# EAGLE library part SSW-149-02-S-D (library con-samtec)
THROUGH-HOLE .025" SQ POST SOCKET Source: Samtec SSW.pdf
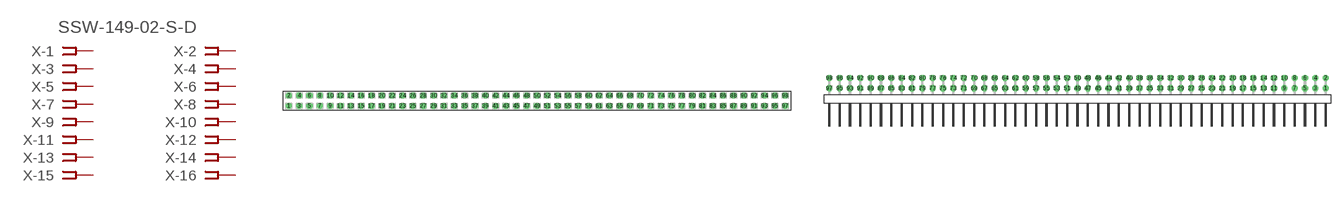
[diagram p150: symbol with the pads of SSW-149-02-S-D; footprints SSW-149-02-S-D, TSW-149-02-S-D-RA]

Designator prefix X; gates -1=FPINV -2=FPIN -3=FPIN -4=FPIN -5=FPIN -6=FPIN -7=FPIN -8=FPIN -9=FPIN -10=FPIN -11=FPIN -12=FPIN -13=FPIN -14=FPIN -15=FPIN -16=FPIN -17=FPIN -18=FPIN -19=FPIN -20=FPIN -21=FPIN -22=FPIN -23=FPIN -24=FPIN -25=FPIN -26=FPIN -27=FPIN -28=FPIN -29=FPIN -30=FPIN -31=FPIN -32=FPIN -33=FPIN -34=FPIN -35=FPIN -36=FPIN -37=FPIN -38=FPIN -39=FPIN -40=FPIN -41=FPIN -42=FPIN -43=FPIN -44=FPIN -45=FPIN -46=FPIN -47=FPIN -48=FPIN -49=FPIN -50=FPIN -51=FPIN -52=FPIN -53=FPIN -54=FPIN -55=FPIN -56=FPIN -57=FPIN -58=FPIN -59=FPIN -60=FPIN -61=FPIN -62=FPIN -63=FPIN -64=FPIN -65=FPIN -66=FPIN -67=FPIN -68=FPIN -69=FPIN -70=FPIN -71=FPIN -72=FPIN -73=FPIN -74=FPIN -75=FPIN -76=FPIN -77=FPIN -78=FPIN -79=FPIN -80=FPIN -81=FPIN -82=FPIN -83=FPIN -84=FPIN -85=FPIN -86=FPIN -87=FPIN -88=FPIN -89=FPIN -90=FPIN -91=FPIN -92=FPIN -93=FPIN -94=FPIN -95=FPIN -96=FPIN -97=FPIN -98=FPIN

## SSW-149-02-S-D (OC_FARNELL: unknown; OC_NEWARK: unknown)  [SSW-149-02-S-D]
1  -1:1  pas
2  -2:1  pas
3  -3:1  pas
4  -4:1  pas
5  -5:1  pas
6  -6:1  pas
7  -7:1  pas
8  -8:1  pas
9  -9:1  pas
10  -10:1  pas
11  -11:1  pas
12  -12:1  pas
13  -13:1  pas
14  -14:1  pas
15  -15:1  pas
16  -16:1  pas
17  -17:1  pas
18  -18:1  pas
19  -19:1  pas
20  -20:1  pas
21  -21:1  pas
22  -22:1  pas
23  -23:1  pas
24  -24:1  pas
25  -25:1  pas
26  -26:1  pas
27  -27:1  pas
28  -28:1  pas
29  -29:1  pas
30  -30:1  pas
31  -31:1  pas
32  -32:1  pas
33  -33:1  pas
34  -34:1  pas
35  -35:1  pas
36  -36:1  pas
37  -37:1  pas
38  -38:1  pas
39  -39:1  pas
40  -40:1  pas
41  -41:1  pas
42  -42:1  pas
43  -43:1  pas
44  -44:1  pas
45  -45:1  pas
46  -46:1  pas
47  -47:1  pas
48  -48:1  pas
49  -49:1  pas
50  -50:1  pas
51  -51:1  pas
52  -52:1  pas
53  -53:1  pas
54  -54:1  pas
55  -55:1  pas
56  -56:1  pas
57  -57:1  pas
58  -58:1  pas
59  -59:1  pas
60  -60:1  pas
61  -61:1  pas
62  -62:1  pas
63  -63:1  pas
64  -64:1  pas
65  -65:1  pas
66  -66:1  pas
67  -67:1  pas
68  -68:1  pas
69  -69:1  pas
70  -70:1  pas
71  -71:1  pas
72  -72:1  pas
73  -73:1  pas
74  -74:1  pas
75  -75:1  pas
76  -76:1  pas
77  -77:1  pas
78  -78:1  pas
79  -79:1  pas
80  -80:1  pas
81  -81:1  pas
82  -82:1  pas
83  -83:1  pas
84  -84:1  pas
85  -85:1  pas
86  -86:1  pas
87  -87:1  pas
88  -88:1  pas
89  -89:1  pas
90  -90:1  pas
91  -91:1  pas
92  -92:1  pas
93  -93:1  pas
94  -94:1  pas
95  -95:1  pas
96  -96:1  pas
97  -97:1  pas
98  -98:1  pas

## SSW-149-02-S-D-RA (MPN: SSW-149-02-S-D-RA; OC_FARNELL: unknown; OC_NEWARK: 12P0058)  [TSW-149-02-S-D-RA]
Pads as for SSW-149-02-S-D

## Footprint SSW-149-02-S-D (pad centres in mm)
THROUGH-HOLE .025" SQ POST SOCKET Source: Samtec SSW.pdf
drill 1 pad 1.5 octagon: 1 -60.96,-1.27; 2 -60.96,1.27; 3 -58.42,-1.27; 4 -58.42,1.27; 5 -55.88,-1.27; 6 -55.88,1.27; 7 -53.34,-1.27; 8 -53.34,1.27; 9 -50.8,-1.27; 10 -50.8,1.27; 11 -48.26,-1.27; 12 -48.26,1.27; 13 -45.72,-1.27; 14 -45.72,1.27; 15 -43.18,-1.27; 16 -43.18,1.27; 17 -40.64,-1.27; 18 -40.64,1.27; 19 -38.1,-1.27; 20 -38.1,1.27; 21 -35.56,-1.27; 22 -35.56,1.27; 23 -33.02,-1.27; 24 -33.02,1.27; 25 -30.48,-1.27; 26 -30.48,1.27; 27 -27.94,-1.27; 28 -27.94,1.27; 29 -25.4,-1.27; 30 -25.4,1.27; 31 -22.86,-1.27; 32 -22.86,1.27; 33 -20.32,-1.27; 34 -20.32,1.27; 35 -17.78,-1.27; 36 -17.78,1.27; 37 -15.24,-1.27; 38 -15.24,1.27; 39 -12.7,-1.27; 40 -12.7,1.27; 41 -10.16,-1.27; 42 -10.16,1.27; 43 -7.62,-1.27; 44 -7.62,1.27; 45 -5.08,-1.27; 46 -5.08,1.27; 47 -2.54,-1.27; 48 -2.54,1.27; 49 0,-1.27; 50 0,1.27; 51 2.54,-1.27; 52 2.54,1.27; 53 5.08,-1.27; 54 5.08,1.27; 55 7.62,-1.27; 56 7.62,1.27; 57 10.16,-1.27; 58 10.16,1.27; 59 12.7,-1.27; 60 12.7,1.27; 61 15.24,-1.27; 62 15.24,1.27; 63 17.78,-1.27; 64 17.78,1.27; 65 20.32,-1.27; 66 20.32,1.27; 67 22.86,-1.27; 68 22.86,1.27; 69 25.4,-1.27; 70 25.4,1.27; 71 27.94,-1.27; 72 27.94,1.27; 73 30.48,-1.27; 74 30.48,1.27; 75 33.02,-1.27; 76 33.02,1.27; 77 35.56,-1.27; 78 35.56,1.27; 79 38.1,-1.27; 80 38.1,1.27; 81 40.64,-1.27; 82 40.64,1.27; 83 43.18,-1.27; 84 43.18,1.27; 85 45.72,-1.27; 86 45.72,1.27; 87 48.26,-1.27; 88 48.26,1.27; 89 50.8,-1.27; 90 50.8,1.27; 91 53.34,-1.27; 92 53.34,1.27; 93 55.88,-1.27; 94 55.88,1.27; 95 58.42,-1.27; 96 58.42,1.27; 97 60.96,-1.27; 98 60.96,1.27

## Footprint TSW-149-02-S-D-RA (pad centres in mm)
THROUGH-HOLE .025" SQ POST HEADER Source: Samtec TSW.pdf
drill 1 pad 1.5 octagon: 1 60.96,1.524; 2 60.96,4.064; 3 58.42,1.524; 4 58.42,4.064; 5 55.88,1.524; 6 55.88,4.064; 7 53.34,1.524; 8 53.34,4.064; 9 50.8,1.524; 10 50.8,4.064; 11 48.26,1.524; 12 48.26,4.064; 13 45.72,1.524; 14 45.72,4.064; 15 43.18,1.524; 16 43.18,4.064; 17 40.64,1.524; 18 40.64,4.064; 19 38.1,1.524; 20 38.1,4.064; 21 35.56,1.524; 22 35.56,4.064; 23 33.02,1.524; 24 33.02,4.064; 25 30.48,1.524; 26 30.48,4.064; 27 27.94,1.524; 28 27.94,4.064; 29 25.4,1.524; 30 25.4,4.064; 31 22.86,1.524; 32 22.86,4.064; 33 20.32,1.524; 34 20.32,4.064; 35 17.78,1.524; 36 17.78,4.064; 37 15.24,1.524; 38 15.24,4.064; 39 12.7,1.524; 40 12.7,4.064; 41 10.16,1.524; 42 10.16,4.064; 43 7.62,1.524; 44 7.62,4.064; 45 5.08,1.524; 46 5.08,4.064; 47 2.54,1.524; 48 2.54,4.064; 49 0,1.524; 50 0,4.064; 51 -2.54,1.524; 52 -2.54,4.064; 53 -5.08,1.524; 54 -5.08,4.064; 55 -7.62,1.524; 56 -7.62,4.064; 57 -10.16,1.524; 58 -10.16,4.064; 59 -12.7,1.524; 60 -12.7,4.064; 61 -15.24,1.524; 62 -15.24,4.064; 63 -17.78,1.524; 64 -17.78,4.064; 65 -20.32,1.524; 66 -20.32,4.064; 67 -22.86,1.524; 68 -22.86,4.064; 69 -25.4,1.524; 70 -25.4,4.064; 71 -27.94,1.524; 72 -27.94,4.064; 73 -30.48,1.524; 74 -30.48,4.064; 75 -33.02,1.524; 76 -33.02,4.064; 77 -35.56,1.524; 78 -35.56,4.064; 79 -38.1,1.524; 80 -38.1,4.064; 81 -40.64,1.524; 82 -40.64,4.064; 83 -43.18,1.524; 84 -43.18,4.064; 85 -45.72,1.524; 86 -45.72,4.064; 87 -48.26,1.524; 88 -48.26,4.064; 89 -50.8,1.524; 90 -50.8,4.064; 91 -53.34,1.524; 92 -53.34,4.064; 93 -55.88,1.524; 94 -55.88,4.064; 95 -58.42,1.524; 96 -58.42,4.064; 97 -60.96,1.524; 98 -60.96,4.064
